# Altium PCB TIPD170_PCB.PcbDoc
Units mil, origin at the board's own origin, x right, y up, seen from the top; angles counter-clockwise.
Board outline 1900 x 1900 mil, 2 copper layers (Top Layer, Bottom Layer); 35 components, 14 nets, 66 pads, 14 vias.
Unrouted connection lines stored in the file: 2.
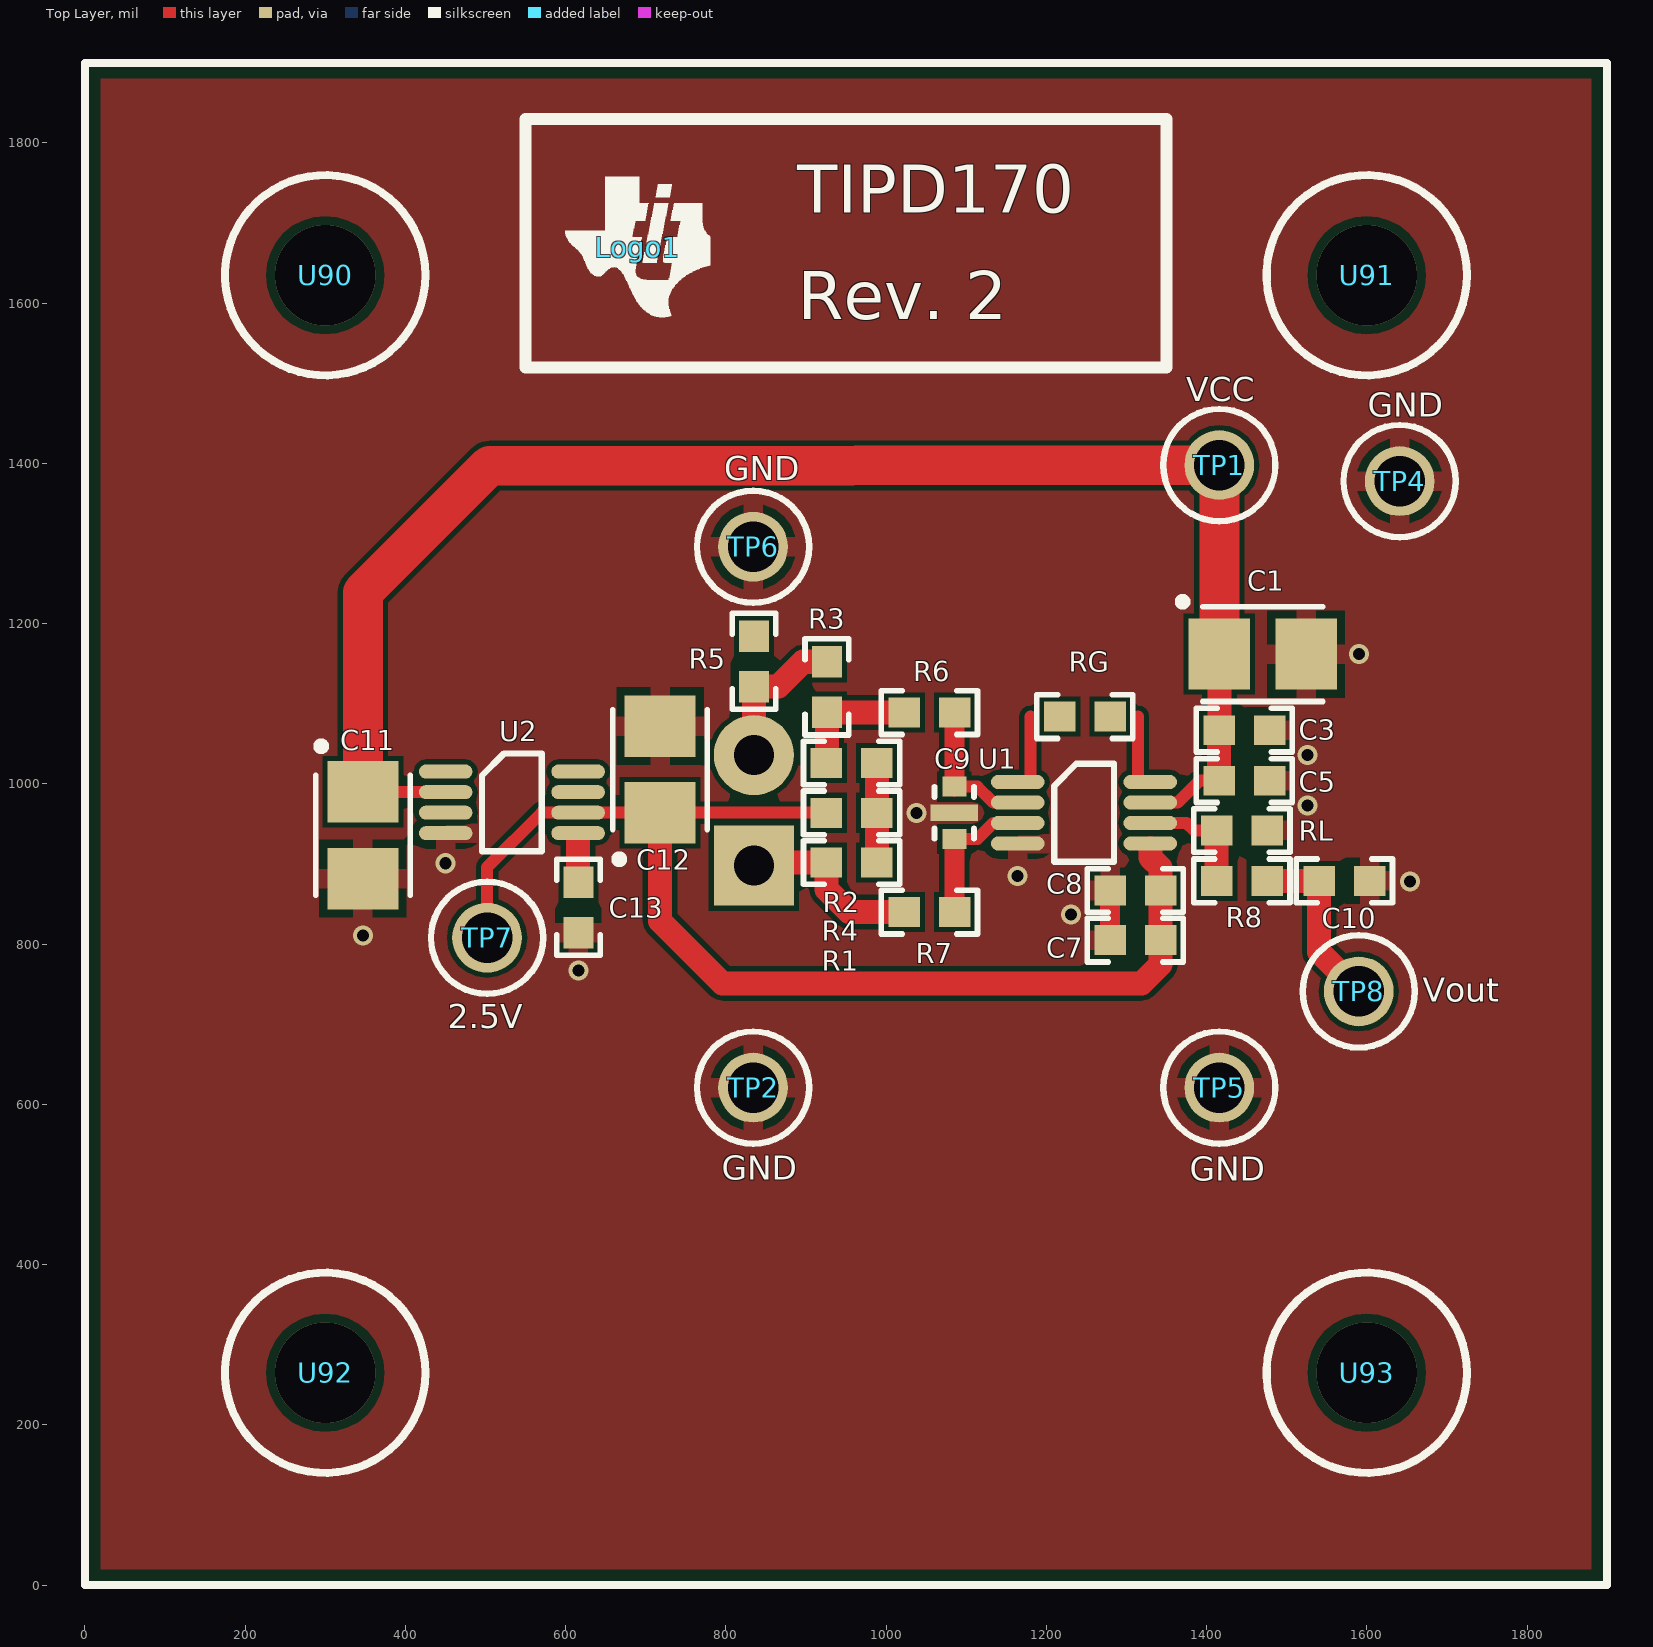
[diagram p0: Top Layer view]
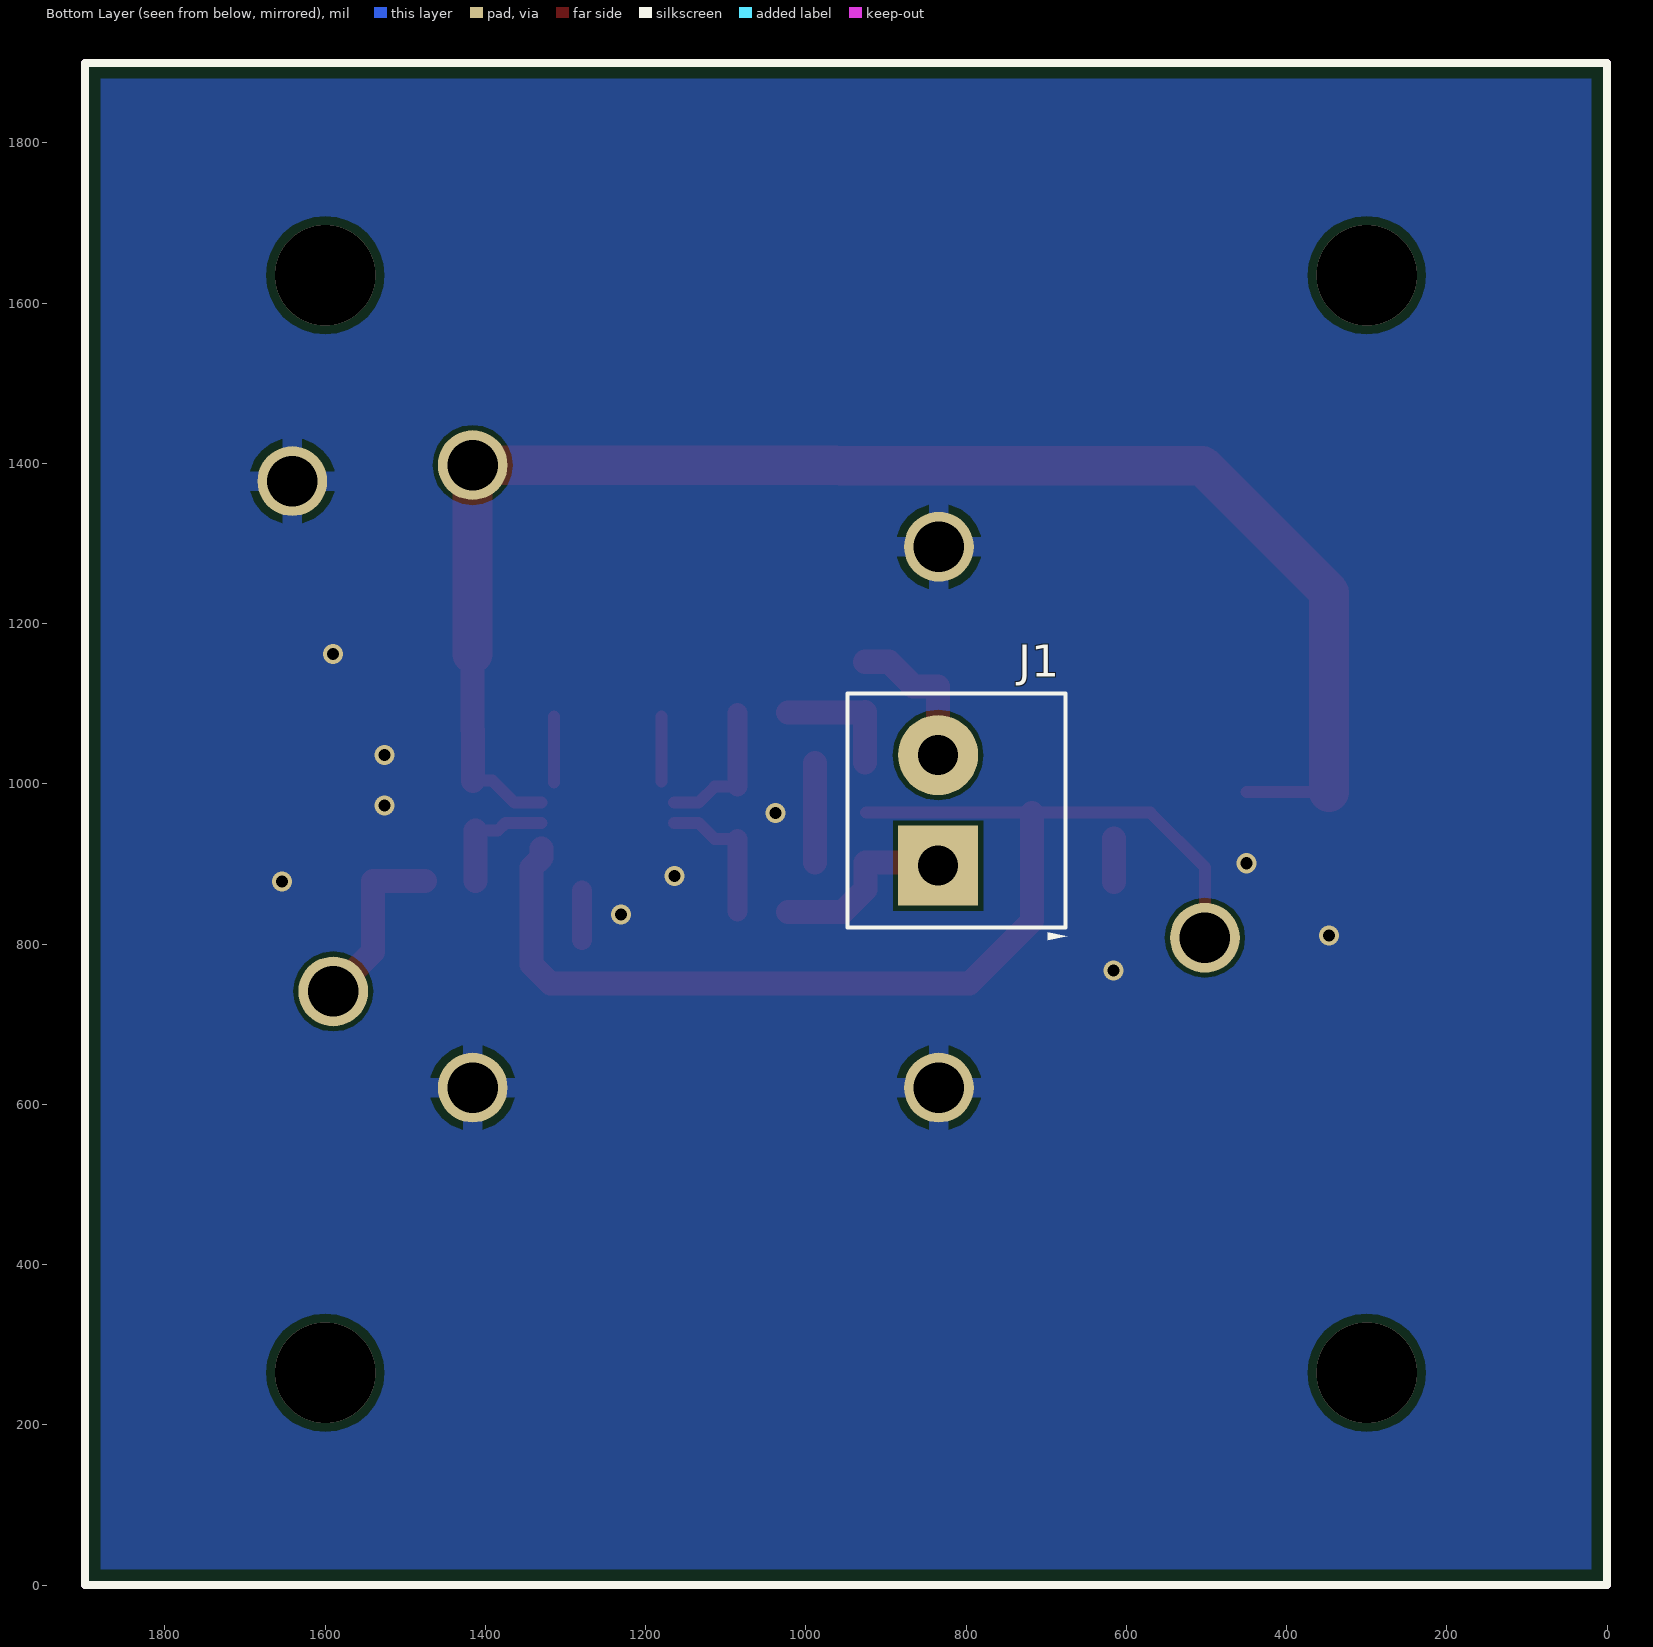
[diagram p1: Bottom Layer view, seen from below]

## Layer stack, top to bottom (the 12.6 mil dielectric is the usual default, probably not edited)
Top Solder: solder mask 0.4, Solder Resist, Dk 3.5
Top Layer: signal copper 1.4
Dielectric1: core 12.6, FR-4, Dk 4.8
Bottom Layer: signal copper 1.4
Bottom Solder: solder mask 0.4, Solder Resist, Dk 3.5

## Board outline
0,0 0,1900 1900,1900 1900,0

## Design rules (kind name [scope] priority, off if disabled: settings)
AcuteAngle [All] p1: minimum=6.00000000000000E+0001 checktracksonly=FALSE
AssemblyTestPointUsage [All] p1 off:
AssemblyTestpoint [All] p1 off: testpointundercomponent=TRUE minsize=40 maxsize=100 preferedsize=60 minholesize=0 maxholesize=40 preferedholesize=32 testpointgrid=1 usegrid=TRUE gridtolerance=0.01 allowsidetop=TRUE allowsidebottom=TRUE
Clearance Clearance_1 [(HasFootprint('STANDOFF HEX 4-40THR ALUM 1"L'))] p1: gap=11
Clearance [All] p2: gap=6
ComponentClearance [All] p1 off: gap=10 collisioncheckmode=3 verticalgap=10 showdistances=FALSE
DiffPairsRouting [All] p1 off: maxlimit=10 minlimit=10 mostfreqgap=10 toplayer_minwidth=15 toplayer_maxwidth=15 toplayer_prefwidth=15 bottomlayer_minwidth=15 bottomlayer_maxwidth=15 bottomlayer_prefwidth=15 maxuncoupledlength=500
FabricationTestPointUsage TestPointUsage [All] p1 off: valid=0 allowmultiple=FALSE
FabricationTestpoint Testpoint [All] p1 off: side=3 testpointundercomponent=TRUE minsize=40 maxsize=100 preferedsize=60 minholesize=0 maxholesize=40 preferedholesize=32 testpointgrid=1 allowsidetop=TRUE allowsidebottom=TRUE usegrid=TRUE gridtolerance=0.01
FanoutControl Fanout_BGA [IsBGA] p1 off: bgadir=Out bgaviamode=Centered fanoutstyle=Auto fanoutdirection=Alternating viagrid=1 // Fanout_BGA (Default Rule)
FanoutControl Fanout_LCC [IsLCC] p2 off: bgadir=Out bgaviamode=Centered fanoutstyle=Auto fanoutdirection=Alternating viagrid=1 // Fanout_LCC (Default Rule)
FanoutControl Fanout_SOIC [IsSOIC] p3 off: bgadir=Out bgaviamode=Centered fanoutstyle=Auto fanoutdirection=Alternating viagrid=1 // Fanout_SOIC (Default Rule)
FanoutControl Fanout_Small [(CompPinCount < 5)] p4 off: bgadir=Out bgaviamode=Centered fanoutstyle=Auto fanoutdirection=OutThenIn viagrid=1 // Fanout_Small (Default Rule)
FanoutControl Fanout_Default [All] p5 off: bgadir=Out bgaviamode=Centered fanoutstyle=Auto fanoutdirection=Alternating viagrid=1 // Fanout_Default (Default Rule)
Height [All] p1 off: minheight=0 maxheight=1000 prefheight=500
HoleSize [All] p1: absolutevalues=TRUE maxlimit=400 minlimit=15 maxpercent=80.000 minpercent=20.000
HoleToHoleClearance [All] p1: gap=8 allowstackedmicrovias=TRUE
LayerPairs [All] p1 off: enforce=FALSE
MinimumAnnularRing [All] p1: minimumring=5
MinimumSolderMaskSliver [All] p1: minsoldermaskwidth=4
PlaneConnect [All] p1: planeconnectstyle=Relief reliefexpansion=20 reliefentries=4 reliefconductorwidth=20 reliefairgap=10
PolygonConnect PolygonConnect_2 [InComponent('C9')] p1: connectstyle=Direct reliefconductorwidth=10 reliefentries=4 polygonreliefangle="90 Angle" airgapwidth=10
PolygonConnect PolygonConnect_1 [(InComponentClass('All Components'))] p2: connectstyle=Relief reliefconductorwidth=25 reliefentries=4 polygonreliefangle="90 Angle" airgapwidth=10
PolygonConnect [All] p3: connectstyle=Direct reliefconductorwidth=25 reliefentries=4 polygonreliefangle="90 Angle" airgapwidth=10
RoutingVias [All] p1: holewidth=15 width=25 viastyle="Through Hole" minholewidth=15 minwidth=25 maxholewidth=400 maxwidth=500
SilkToSilkClearance [All] p1: silktosilkclearance=5
SilkToSolderMaskClearance SilkscreenOverComponentPads [IsPad] p1: minsilkscreentomaskgap=5 clearancetoexposedcopper=TRUE
SolderMaskExpansion [All] p1: expansion=2
UnpouredPolygon [All] p1: allowunpoured=FALSE
Width [All] p1: maxlimit=100 minlimit=6 preferedwidth=15
10 further rules are at their usual default settings.

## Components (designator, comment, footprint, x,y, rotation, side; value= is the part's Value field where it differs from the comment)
C1 "TPSB106M020R1000" 3528-21 1470.13,1162 r0 top
C3 "GRM188R71E105KA12D" 0603 1447.13,1067 r0 top
C5 "0603YC104JAT2A" 0603 1447.13,1004 r0 top
C7 "GRM188R71E105KA12D" 0603 1311.13,805 r180 top
C8 "0603YC104JAT2A" 0603 1311.13,867 r180 top
C9 "CX0603MRX7R0BB102" X2Y_0603 1085.13,964 r270 top
C10 "0603YC104JAT2A" 0603 1572.13,879 r0 top
C11 "TPSB106M020R1000" 3528-21 347,936 r270 top
C12 "TPSB106M020R1000" 3528-21 718,1018 r90 top
C13 "GRM188R71E105KA12D" 0603 616,846 r270 top
J1 "ED555/2DS" TERM_BLK_ED555-2DS 835,898 r90 bottom
Logo1 "Texas Instruments" TI_Symbol_Overlay_Small 690,1670 r0 top
R1 "RG1608P-121-B-T5" 0603 957,902 r0 top
R2 "RG1608P-121-B-T5" 0603 957,1026 r0 top
R3 "RG1608P-121-B-T5" 0603 926,1121 r270 top
R4 "CRCW06030000Z0EA" 0603 957,964 r180 top
R5 "CRCW06031K27FKEA" 0603 835,1153 r270 top
R6 "CRCW06030000Z0EA" 0603 1054.13,1089 r180 top
R7 "CRCW06030000Z0EA" 0603 1054.13,840 r180 top
R8 "CRCW06030000Z0EA" 0603 1444.13,879 r0 top
RG "RC0603FR-07100RL" 0603 1248.13,1084 r180 top (schematic designator Rg)
RL "CRCW060310K0FKEA" 0603 1444.13,942 r180 top (schematic designator Rl)
TP1 "VCC" Keystone5005 1416,1398 r0 top
TP2 "GND" Keystone5006 834,621 r90 top
TP4 "GND" Keystone5006 1641,1378 r90 top
TP5 "GND" Keystone5006 1416,621 r90 top
TP6 "GND" Keystone5006 834,1296 r90 top
TP7 "2.5V" Keystone5008 502,808 r270 top
TP8 "Vout" Keystone5007 1590,741 r0 top
U1 "INA333AIDGK" DGK0008A_N 1247.13,964 r0 top
U2 "REF5025AIDGKR" DGK0008A_N 533,977 r0 top
U90 "Standoff" "STANDOFF HEX 4-40THR ALUM 1\"L" 300,1635 r0 top
U91 "Standoff" "STANDOFF HEX 4-40THR ALUM 1\"L" 1600,1635 r0 top
U92 "Standoff" "STANDOFF HEX 4-40THR ALUM 1\"L" 300,265 r0 top
U93 "Standoff" "STANDOFF HEX 4-40THR ALUM 1\"L" 1600,265 r0 top

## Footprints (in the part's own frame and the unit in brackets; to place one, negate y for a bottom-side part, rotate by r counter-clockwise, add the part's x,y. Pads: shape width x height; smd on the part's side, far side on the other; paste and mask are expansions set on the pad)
0603 [mm] "0603 from SM-752 data"
  rect 1x0.95 smd: 1(-0.8,0) 2(0.8,0)
  silkscreen extent -1.52,-0.69 1.52,0.69, body extent -0.87,-0.47 0.87,0.47, height 0.85
3528-21 [mm] "Medium Density IPC, based on SM-782 section 8.4"
  rect 1.95x2.25 smd: 1(-1.375,0) 2(1.375,0)
  silkscreen extent -2.66,-1.5 1.9,1.79, body extent -1.85,-1.5 1.85,1.5, height 2.1
DGK0008A_N [mm] "TSOP, 8-Leads, Body 3x3mm, Pitch 0.65mm, IPC Medium Density"
  oval 1.7x0.45 smd mask+0.05: 1(-2.1,0.975) 2(-2.1,0.325) 3(-2.1,-0.325) 4(-2.1,-0.975) 5(2.1,-0.975) 6(2.1,-0.325) 7(2.1,0.325) 8(2.1,0.975)
  silkscreen extent -0.95,-1.55 0.95,1.55, body extent -2.45,-1.5 2.45,1.5, height 0.94
Keystone5005 [mil] "Keystone Compact loops"
  round 87 hole 63: 1(0,0)
  silkscreen extent -70,-70 70,70, body extent -63,-63 62,63, height 225
Keystone5006 [mil] "Keystone Compact loops"
  round 87 hole 63: 1(0,0)
  silkscreen extent -70,-70 70,70, body extent -63,-63 62,63, height 225
Keystone5007 [mil] "Keystone Compact loops"
  round 87 hole 63: 1(0,0)
  silkscreen extent -70,-70 70,70, body extent -63,-63 62,63, height 225
Keystone5008 [mil] "Keystone Compact loops"
  round 87 hole 63: 1(0,0)
  silkscreen extent -70,-70 70,70, body extent -63,-63 62,63, height 225
"STANDOFF HEX 4-40THR ALUM 1\"L" [mil] "STANDOFF HEX 4-40THR ALUM 1\"L"
  silkscreen extent -125,-125 125,125
TERM_BLK_ED555-2DS [mil]
  rect 100x100 hole 50: 1(0,0)
  round 100 hole 50: 2(138,0)
  silkscreen extent -93,-161 215,113, body extent -69,-150 207,106, height 323
TI_Symbol_Overlay_Small [mil]
  silkscreen extent -90,-88 91,88
X2Y_0603 [mm]
  rect 0.64x0.76 smd: 1(-0.83,0) 2(0.83,0)
  rect 0.51x1.52 smd: 3(0,0)
  silkscreen extent -0.82,-0.63 0.82,0.63, body extent -0.88,-0.51 0.88,0.51, height 0.75

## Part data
C1 C11 C12: "CAP, TANT, 10uF, 20V, +/-20%, 1 ohm, 3528-21 SMD"
C3 C7 C13: "CAP, CERM, 1uF, 25V, +/-10%, X7R, 0603"
C5 C8 C10: "CAP, CERM, 0.1uF, 16V, +/-5%, X7R, 0603"
C9: "CAP, CERM, 1000 pF, 100 V, +/- 20%, X7R, 0603"
J1: "Terminal Block, 6A, 3.5mm Pitch, 2-Pos, TH"
Logo1: library part TI_Logo, "Texas Instrument Corporate Signature"
R1 R2 R3: "RES, 120, 0.1%, 0.1 W, 0603"
R4 R6 R7 R8: "RES, 0, 5%, 0.1 W, 0603"
R5: "RES, 1.27 k, 1%, 0.1 W, 0603"
RG: "RES, 100 ohm, 1%, 0.1W, 0603"
RL: "RES, 10.0k ohm, 1%, 0.1W, 0603"
TP1: library part 5005, "Test Point, TH, Compact, Red"
TP2 TP4 TP5 TP6: library part 5006, "Test Point, TH, Compact, Black"
TP7: library part 5008, "Test Point, Compact, Orange, TH"
TP8: library part 5007, "Test Point, Compact, White, TH"
U1: "Micro-Power (50mA), Zerø-Drift, Rail-to-Rail Out Instrumentation Amplifier"
U2: "Low Noise, Very Low Drift, Precision Voltage Reference, -40 to 125 degC, 8-pin MSOP(DGK), Green (RoHS & no Sb/Br)"
U90 U91 U92 U93: library part "Standoff, 1\", 4-40, Alum, F-F", "STANDOFF HEX 4-40THR ALUM 1\"L"

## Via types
v1: diameter 25, hole 15, Top Layer to Bottom Layer, 10 vias
v2: diameter 125, hole 125, Top Layer to Bottom Layer, 4 vias

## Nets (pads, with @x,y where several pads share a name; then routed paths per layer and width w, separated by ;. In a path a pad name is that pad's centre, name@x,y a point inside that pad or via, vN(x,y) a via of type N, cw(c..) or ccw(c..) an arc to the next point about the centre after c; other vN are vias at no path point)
2.5V: C7.1 C8.1 C12.1 R4.2 TP7.1 U1.5 U2.6 | length 1491.1
  Top Layer w15: TP7.1 502,896 570.2,964.2 U2.6 R4.2@925.3,964.2
  Top Layer w30: C12.1 718,829 796,751 1319,751 1342.63,774.63 C7.1 C8.1 1342.63,895.5 1329.81,908.32 U1.5@1329.81,919.32
GND: C1.2 C3.2 C5.2 C7.2 C8.2 C9.3 C10.2 C11.2 C12.2 C13.2 R5.1 RL.1 TP2.1 TP4.1 TP5.1 TP6.1 U1.4 U2.4 | length 62
  Top Layer w25: C7.2 C8.2
  other v1: 616,767 347,811 1231,837 1654,878 1164,885 450,901 1038,964 1526,973 1526,1036 1590,1162
NetC9_1: C9.1 R6.1 U1.2 | length 179.4
  Top Layer w15: C9.1 1113.94,996.68 1133.82,976.8 U1.2
  Top Layer w25: C9.1 R6.1@1085.13,1088.5
NetC9_2: C9.2 R7.1 U1.3 | length 178.4
  Top Layer w15: C9.2 1113.94,931.32 1133.82,951.2 U1.3
  Top Layer w25: R7.1@1085.13,840.5 C9.2
NetC10_1: C10.1 R8.2 TP8.1 | length 223.5
  Top Layer w30: R8.2 C10.1 1540.64,790.36 TP8.1
NetC13_1: C13.1 U2.5 | length 54.2
  Top Layer w30: C13.1@615.68,877.82 U2.5@615.68,932
NetJ1_1: J1.1 R1.1 R7.2 | length 228.9
  Top Layer w30: J1.1@839,902 R1.1 925.5,868.5 954,840 R7.2
NetJ1_2: J1.2 R3.1 R5.2 | length 189.3
  Top Layer w30: J1.2 R5.2 865.5,1121.5 896.5,1152.5 R3.1
NetR1_2: R1.2 R2.2 R4.1 | length 124
  Top Layer w30: R1.2 R4.1 R2.2
NetR2_1: R2.1 R3.2 R6.2 | length 159.1
  Top Layer w30: R2.1@926,1026.5 R3.2 ; R3.2@926.5,1089 R6.2
NetR8_1: R8.1 RL.2 U1.6 | length 149.6
  Top Layer w15: U1.6 1374.93,951.2 1384.13,942 RL.2
  Top Layer w30: R8.1 RL.2
NetRG_1: RG.1 U1.8 | length 81.9
  Top Layer w15: U1.8@1314.22,1002.09 1314.22,1084
NetRG_2: RG.2 U1.1 | length 81.1
  Top Layer w15: U1.1@1180.05,1002.91 1180.05,1084
VCC: C1.1 C3.1 C5.1 C11.1 TP1.1 U1.7 U2.2 | length 1977
  Top Layer w15: C11.1@347.34,989.8 U2.2 ; U1.7 1363.93,976.8 1391.13,1004 C5.1
  Top Layer w30: C5.1 C3.1 ; C3.1@1416,1067.36 C1.1
  Top Layer w50: C11.1 347,1239 505,1397 TP1.1 C1.1
pads on no net: U2.1 U2.3 U2.7 U2.8
copper on no net: | length 15200
  Top Layer w10: 0,0 1900,0 1900,1900 0,1900 0,0
  Bottom Layer w10: 0,0 0,1900 1900,1900 1900,0 0,0
  other v2: 300,265 1600,265 300,1635 1600,1635

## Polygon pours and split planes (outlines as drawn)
GND on Top Layer "Top Layer-No Net" (solid, remove dead copper, pour order 2): 20,1880 1880,1880 1880,20 20,20
GND on Bottom Layer "Bottom Layer-No Net" (solid, remove dead copper, pour order 4): 20,1880 1880,1880 1880,20 20,20

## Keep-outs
Keep-Out Layer:
  the board outline again, w10

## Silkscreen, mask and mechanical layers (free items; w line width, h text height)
Top Overlay:
  lines w10: 0,0 0,1900 1900,1900 1900,0 0,0
  lines w15: 550,1520 1350,1520 1350,1830 550,1830 550,1520
  text "TIPD170" at 889,1713 h60
  text "Rev. 2" at 890,1580 h60
Bottom Overlay:
  the board outline again, w10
